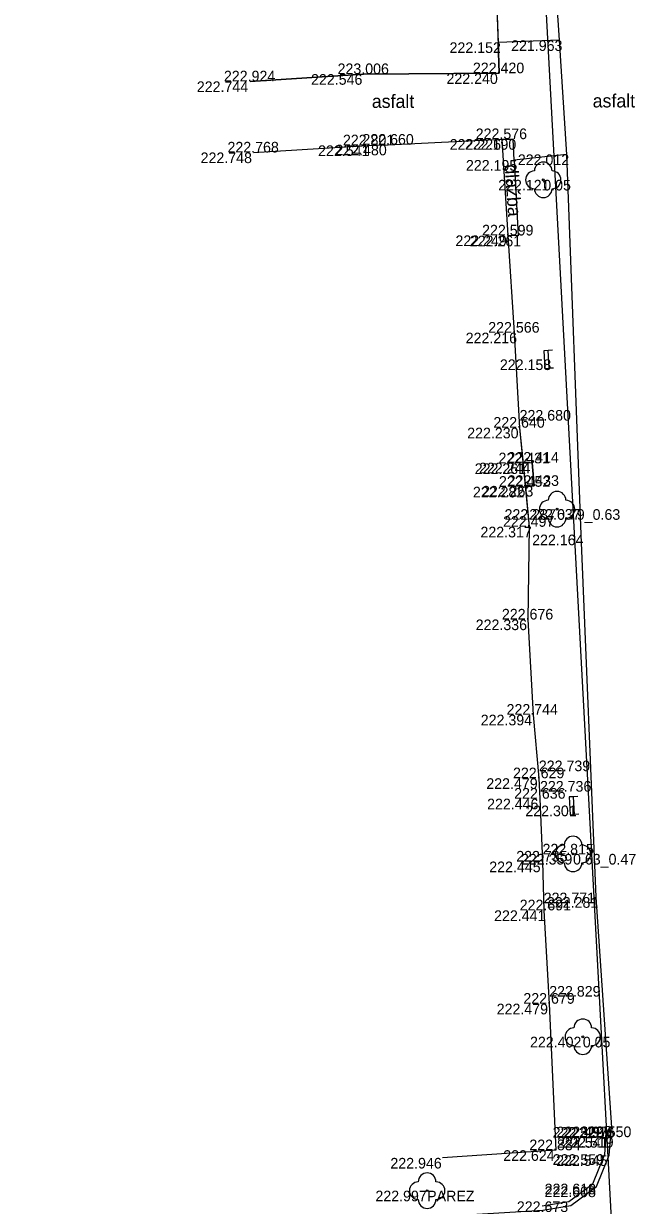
# Model space of a CAD drawing. Extents: x -599516 to -599132, y -1163668 to -1163119.
# Drawn here: x -599301.88 to -599284.57, y -1163560.2 to -1163526.85 of the extents above; entities that cross this region are included whole.
import ezdxf

# ---------------------------------------------------------------- set-up
doc = ezdxf.new("R2010")
doc.units = 0
for name, color, linetype in [('_ZEMERENI OBLAST', 7, 'Continuous'), ('Bod-oznac1', 7, 'Continuous'), ('Bod-oznac2', 7, 'Continuous'), ('Bod-oznac3', 7, 'Continuous'), ('Bod-vyska1', 7, 'Continuous'), ('Bod-vyska2', 7, 'Continuous'), ('Bod-vyska3', 7, 'Continuous'), ('Z_cela-hrobu-dolni-linie', 7, 'Continuous'), ('Z_cela-hrobu-horni-linie', 7, 'Continuous'), ('Z_chodnik', 7, 'Continuous'), ('Z_komunikace', 7, 'Continuous'), ('Z_nove-stromy-prumer-kmene', 7, 'Continuous'), ('Z_obvod-kmene-spodek-ve-vysce1_2m', 7, 'Continuous'), ('Z_parez-stromu', 7, 'Continuous'), ('Z_popis-budov-povrchu', 7, 'Continuous'), ('Z_stromy-kere', 7, 'Continuous'), ('Z_stromy-nove-vysazene', 7, 'Continuous'), ('Z_vol-lin-obrubnik', 7, 'Continuous'), ('Z_znacky-ostatni-lavicka', 7, 'Continuous'), ('Z_zpevnene-plochy', 7, 'Continuous')]:
    doc.layers.add(name, color=color, linetype=linetype)

msp = doc.modelspace()

# ---------------------------------------------------------------- linework, layer by layer
at = {"layer": '_ZEMERENI OBLAST'}
msp.add_lwpolyline([(-599497.946, -1163390.674), (-599491.96, -1163502.01), (-599489.976, -1163538.978), (-599287.834, -1163513.31), (-599283.12, -1163600.69), (-599345.275, -1163603.707), (-599342.31, -1163660.29), (-599277.306, -1163657.294), (-599220.632, -1163654.171)], dxfattribs=at)
at = {"layer": 'Bod-oznac1'}
for p, q in [((-599288.47, -1163527.374), (-599288.47, -1163527.374)), ((-599286.754, -1163527.316), (-599286.754, -1163527.316)), ((-599292.277, -1163528.271), (-599292.277, -1163528.271)), ((-599288.443, -1163528.247), (-599288.443, -1163528.247)), ((-599295.479, -1163528.477), (-599295.479, -1163528.477)), ((-599292.171, -1163530.282), (-599292.171, -1163530.282)), ((-599291.58, -1163530.263), (-599291.58, -1163530.263)), ((-599288.373, -1163530.106), (-599288.373, -1163530.106)), ((-599288.05, -1163530.105), (-599288.05, -1163530.105)), ((-599295.383, -1163530.483), (-599295.383, -1163530.483)), ((-599286.543, -1163530.537), (-599286.543, -1163530.537)), ((-599288.019, -1163530.696), (-599288.019, -1163530.696)), ((-599287.2, -1163531.255), (-599287.2, -1163531.255)), ((-599288.199, -1163532.825), (-599288.199, -1163532.825)), ((-599287.91, -1163532.832), (-599287.91, -1163532.832)), ((-599288.026, -1163535.569), (-599288.026, -1163535.569)), ((-599287.048, -1163536.324), (-599287.048, -1163536.324)), ((-599287.869, -1163538.251), (-599287.869, -1163538.251)), ((-599287.771, -1163539.258), (-599287.771, -1163539.258)), ((-599287.511, -1163539.239), (-599287.511, -1163539.239)), ((-599287.706, -1163539.919), (-599287.706, -1163539.919)), ((-599287.461, -1163539.894), (-599287.461, -1163539.894)), ((-599286.811, -1163540.551), (-599286.811, -1163540.551)), ((-599287.596, -1163541.048), (-599287.596, -1163541.048)), ((-599286.137, -1163541.269), (-599286.137, -1163541.269)), ((-599287.639, -1163543.665), (-599287.639, -1163543.665)), ((-599287.484, -1163546.353), (-599287.484, -1163546.353)), ((-599287.326, -1163548.146), (-599287.326, -1163548.146)), ((-599287.293, -1163548.723), (-599287.293, -1163548.723)), ((-599286.331, -1163548.917), (-599286.331, -1163548.917)), ((-599286.36, -1163550.281), (-599286.36, -1163550.281)), ((-599287.222, -1163550.497), (-599287.222, -1163550.497)), ((-599285.718, -1163551.502), (-599285.718, -1163551.502)), ((-599287.189, -1163551.875), (-599287.189, -1163551.875)), ((-599287.033, -1163554.51), (-599287.033, -1163554.51)), ((-599286.084, -1163555.443), (-599286.084, -1163555.443)), ((-599285.466, -1163557.993), (-599285.466, -1163557.993)), ((-599285.422, -1163558.275), (-599285.422, -1163558.275)), ((-599285.344, -1163557.979), (-599285.344, -1163557.979)), ((-599285.299, -1163558.271), (-599285.299, -1163558.271)), ((-599285.275, -1163558), (-599285.275, -1163558)), ((-599290.048, -1163558.861), (-599290.048, -1163558.861)), ((-599286.848, -1163558.645), (-599286.848, -1163558.645)), ((-599285.465, -1163558.758), (-599285.465, -1163558.758)), ((-599285.344, -1163558.787), (-599285.344, -1163558.787)), ((-599285.796, -1163559.59), (-599285.796, -1163559.59)), ((-599290.48, -1163559.787), (-599290.48, -1163559.787)), ((-599285.695, -1163559.669), (-599285.695, -1163559.669)), ((-599286.475, -1163560.089), (-599286.475, -1163560.089))]:
    msp.add_line(p, q, dxfattribs=at)
at = {"layer": 'Bod-oznac2'}
for p, q in [((-599292.277, -1163528.271), (-599292.277, -1163528.271)), ((-599288.443, -1163528.247), (-599288.443, -1163528.247)), ((-599295.479, -1163528.477), (-599295.479, -1163528.477)), ((-599292.171, -1163530.282), (-599292.171, -1163530.282)), ((-599291.58, -1163530.263), (-599291.58, -1163530.263)), ((-599288.373, -1163530.106), (-599288.373, -1163530.106)), ((-599295.383, -1163530.483), (-599295.383, -1163530.483)), ((-599288.199, -1163532.825), (-599288.199, -1163532.825)), ((-599288.026, -1163535.569), (-599288.026, -1163535.569)), ((-599287.869, -1163538.251), (-599287.869, -1163538.251)), ((-599287.771, -1163539.258), (-599287.771, -1163539.258)), ((-599287.511, -1163539.239), (-599287.511, -1163539.239)), ((-599287.706, -1163539.919), (-599287.706, -1163539.919)), ((-599287.461, -1163539.894), (-599287.461, -1163539.894)), ((-599287.596, -1163541.048), (-599287.596, -1163541.048)), ((-599287.639, -1163543.665), (-599287.639, -1163543.665)), ((-599287.484, -1163546.353), (-599287.484, -1163546.353)), ((-599287.326, -1163548.146), (-599287.326, -1163548.146)), ((-599287.293, -1163548.723), (-599287.293, -1163548.723)), ((-599287.222, -1163550.497), (-599287.222, -1163550.497)), ((-599287.189, -1163551.875), (-599287.189, -1163551.875)), ((-599287.033, -1163554.51), (-599287.033, -1163554.51)), ((-599285.422, -1163558.275), (-599285.422, -1163558.275)), ((-599286.848, -1163558.645), (-599286.848, -1163558.645))]:
    msp.add_line(p, q, dxfattribs=at)
at = {"layer": 'Bod-oznac3'}
for p, q in [((-599287.869, -1163538.251), (-599287.869, -1163538.251)), ((-599287.596, -1163541.048), (-599287.596, -1163541.048)), ((-599287.326, -1163548.146), (-599287.326, -1163548.146)), ((-599287.293, -1163548.723), (-599287.293, -1163548.723)), ((-599287.222, -1163550.497), (-599287.222, -1163550.497)), ((-599287.189, -1163551.875), (-599287.189, -1163551.875)), ((-599287.033, -1163554.51), (-599287.033, -1163554.51))]:
    msp.add_line(p, q, dxfattribs=at)
at = {"layer": 'Z_cela-hrobu-dolni-linie'}
for points in [[(-599289.572, -1163505.857), (-599289.403, -1163508.572), (-599289.336, -1163509.711), (-599289.308, -1163510.254), (-599289.258, -1163511.445), (-599289.147, -1163514.133), (-599289.014, -1163515.172), (-599288.989, -1163516.052), (-599288.949, -1163517.063), (-599288.92, -1163517.922), (-599288.855, -1163518.98), (-599288.811, -1163519.843), (-599288.746, -1163520.956), (-599288.724, -1163521.528), (-599288.689, -1163522.629), (-599288.546, -1163525.359), (-599288.47, -1163527.374), (-599288.443, -1163528.247)], [(-599288.373, -1163530.106), (-599288.199, -1163532.825), (-599288.026, -1163535.569), (-599287.869, -1163538.251), (-599287.771, -1163539.258), (-599287.706, -1163539.919), (-599287.596, -1163541.048), (-599287.639, -1163543.665), (-599287.484, -1163546.353), (-599287.326, -1163548.146), (-599287.293, -1163548.723), (-599287.222, -1163550.497), (-599287.189, -1163551.875), (-599287.033, -1163554.51), (-599286.848, -1163558.645), (-599290.048, -1163558.861)]]:
    msp.add_lwpolyline(points, dxfattribs=at)
at = {"layer": 'Z_cela-hrobu-horni-linie'}
for points in [[(-599288.546, -1163525.359), (-599288.443, -1163528.247), (-599292.277, -1163528.271)], [(-599292.277, -1163528.271), (-599295.479, -1163528.477)], [(-599295.383, -1163530.483), (-599292.171, -1163530.282), (-599291.58, -1163530.263), (-599288.373, -1163530.106), (-599288.199, -1163532.825), (-599288.026, -1163535.569), (-599287.869, -1163538.251), (-599287.869, -1163538.251), (-599287.596, -1163541.048), (-599287.596, -1163541.048), (-599287.639, -1163543.665), (-599287.484, -1163546.353), (-599287.326, -1163548.146), (-599287.326, -1163548.146), (-599287.293, -1163548.723), (-599287.293, -1163548.723), (-599287.222, -1163550.497), (-599287.222, -1163550.497), (-599287.189, -1163551.875), (-599287.189, -1163551.875), (-599287.033, -1163554.51), (-599287.033, -1163554.51), (-599286.848, -1163558.645), (-599290.048, -1163558.861)]]:
    msp.add_lwpolyline(points, dxfattribs=at)
at = {"layer": 'Z_chodnik'}
for points in [[(-599295.479, -1163528.477), (-599292.277, -1163528.271), (-599288.443, -1163528.247), (-599288.47, -1163527.374)], [(-599286.754, -1163527.316), (-599288.47, -1163527.374)], [(-599295.383, -1163530.483), (-599292.171, -1163530.282), (-599291.58, -1163530.263), (-599288.373, -1163530.106), (-599288.05, -1163530.105)], [(-599286.543, -1163530.537), (-599288.019, -1163530.696), (-599288.05, -1163530.105)]]:
    msp.add_lwpolyline(points, dxfattribs=at)
at = {"layer": 'Z_komunikace'}
for points in [[(-599289.978, -1163500.153), (-599289.346, -1163500.218), (-599288.913, -1163500.474), (-599288.386, -1163501.431), (-599288.16, -1163505.442), (-599288.036, -1163507.473), (-599287.478, -1163516.528), (-599286.754, -1163527.316), (-599286.543, -1163530.537), (-599286.137, -1163541.269), (-599285.718, -1163551.502), (-599285.275, -1163558)], [(-599291.24, -1163560.577), (-599287.217, -1163560.34), (-599286.426, -1163560.206), (-599285.695, -1163559.669), (-599285.344, -1163558.787), (-599285.275, -1163558)]]:
    msp.add_lwpolyline(points, dxfattribs=at)
at = {"layer": 'Z_parez-stromu'}
msp.add_circle((-599290.48, -1163559.787), 0.025, dxfattribs=at)
for centre, start, end in [((-599290.48, -1163559.537), 0, 180), ((-599290.73, -1163559.787), 90, 270), ((-599290.23, -1163559.787), 270, 90), ((-599290.48, -1163560.037), 180, 0)]:
    msp.add_arc(centre, 0.25, start, end, dxfattribs=at)
at = {"layer": 'Z_stromy-kere'}
for centre in [(-599286.811, -1163540.551), (-599286.36, -1163550.281)]:
    msp.add_circle(centre, 0.025, dxfattribs=at)
for centre, start, end in [((-599286.811, -1163540.301), 0, 180), ((-599287.061, -1163540.551), 90, 270), ((-599286.561, -1163540.551), 270, 90), ((-599286.811, -1163540.801), 180, 0), ((-599286.36, -1163550.031), 0, 180), ((-599286.61, -1163550.281), 90, 270), ((-599286.11, -1163550.281), 270, 90), ((-599286.36, -1163550.531), 180, 0)]:
    msp.add_arc(centre, 0.25, start, end, dxfattribs=at)
at = {"layer": 'Z_stromy-nove-vysazene'}
for centre in [(-599287.2, -1163531.255), (-599286.084, -1163555.443)]:
    msp.add_circle(centre, 0.025, dxfattribs=at)
for centre, start, end in [((-599287.2, -1163531.005), 0, 180), ((-599287.45, -1163531.255), 90, 270), ((-599286.95, -1163531.255), 270, 90), ((-599287.2, -1163531.505), 180, 0), ((-599286.084, -1163555.193), 0, 180), ((-599286.334, -1163555.443), 90, 270), ((-599285.834, -1163555.443), 270, 90), ((-599286.084, -1163555.693), 180, 0)]:
    msp.add_arc(centre, 0.25, start, end, dxfattribs=at)
at = {"layer": 'Z_vol-lin-obrubnik'}
for points in [[(-599287.233, -1163560.217), (-599286.475, -1163560.089), (-599285.796, -1163559.59), (-599285.465, -1163558.758), (-599285.422, -1163558.275)], [(-599285.344, -1163557.979), (-599285.466, -1163557.993), (-599285.422, -1163558.275)], [(-599285.344, -1163557.979), (-599285.299, -1163558.271)]]:
    msp.add_lwpolyline(points, dxfattribs=at)
at = {"layer": 'Z_znacky-ostatni-lavicka'}
for p, q in [((-599286.937, -1163536.067), (-599287.062, -1163536.074)), ((-599286.909, -1163536.567), (-599287.034, -1163536.574)), ((-599286.22, -1163548.66), (-599286.345, -1163548.667)), ((-599286.192, -1163549.16), (-599286.317, -1163549.167))]:
    msp.add_line(p, q, dxfattribs=at)
for points in [[(-599287.159, -1163536.581), (-599287.034, -1163536.574), (-599287.062, -1163536.074), (-599287.187, -1163536.081)], [(-599286.442, -1163549.174), (-599286.317, -1163549.167), (-599286.345, -1163548.667), (-599286.47, -1163548.674)]]:
    msp.add_lwpolyline(points, close=True, dxfattribs=at)
at = {"layer": 'Z_zpevnene-plochy'}
for p, q in [((-599287.511, -1163539.239), (-599287.771, -1163539.258)), ((-599287.461, -1163539.894), (-599287.706, -1163539.919))]:
    msp.add_line(p, q, dxfattribs=at)
for points in [[(-599288.019, -1163530.696), (-599287.91, -1163532.832), (-599288.199, -1163532.825)], [(-599287.706, -1163539.919), (-599287.461, -1163539.894), (-599287.511, -1163539.239), (-599287.771, -1163539.258)], [(-599287.511, -1163539.239), (-599287.461, -1163539.894)]]:
    msp.add_lwpolyline(points, dxfattribs=at)

# ---------------------------------------------------------------- texts
at = {"layer": 'Bod-vyska1'}
for s, p in [('222.152', (-599289.848, -1163527.674)), ('221.963', (-599288.109, -1163527.616)), ('222.546', (-599293.759, -1163528.571)), ('222.240', (-599289.934, -1163528.547)), ('222.744', (-599296.985, -1163528.777)), ('222.541', (-599293.56, -1163530.582)), ('222.480', (-599293.071, -1163530.563)), ('222.226', (-599289.843, -1163530.406)), ('222.190', (-599289.414, -1163530.405)), ('222.748', (-599296.878, -1163530.783)), ('222.012', (-599287.919, -1163530.837)), ('222.195', (-599289.385, -1163530.996)), ('222.121', (-599288.474, -1163531.555)), ('222.249', (-599289.681, -1163533.125)), ('222.261', (-599289.276, -1163533.132)), ('222.216', (-599289.392, -1163535.869)), ('222.158', (-599288.426, -1163536.624)), ('222.230', (-599289.349, -1163538.551)), ('222.261', (-599289.137, -1163539.558)), ('222.244', (-599289.015, -1163539.539)), ('222.282', (-599289.188, -1163540.219)), ('222.263', (-599288.931, -1163540.194)), ('222.237', (-599288.294, -1163540.851)), ('222.317', (-599288.975, -1163541.348)), ('222.164', (-599287.515, -1163541.569)), ('222.336', (-599289.109, -1163543.965)), ('222.394', (-599288.966, -1163546.653)), ('222.479', (-599288.809, -1163548.446)), ('222.446', (-599288.786, -1163549.023)), ('222.301', (-599287.707, -1163549.217)), ('222.359', (-599287.83, -1163550.581)), ('222.445', (-599288.726, -1163550.797)), ('222.281', (-599287.096, -1163551.802)), ('222.441', (-599288.589, -1163552.175)), ('222.479', (-599288.516, -1163554.81)), ('222.402', (-599287.575, -1163555.743)), ('222.529', (-599286.936, -1163558.293)), ('222.497', (-599286.827, -1163558.279)), ('222.541', (-599286.811, -1163558.575)), ('222.519', (-599286.665, -1163558.571)), ('222.516', (-599286.641, -1163558.3)), ('222.946', (-599291.518, -1163559.161)), ('222.624', (-599288.33, -1163558.945)), ('222.559', (-599286.935, -1163559.058)), ('222.545', (-599286.837, -1163559.087)), ('222.618', (-599287.162, -1163559.89)), ('222.997', (-599291.941, -1163560.087)), ('222.608', (-599287.163, -1163559.969)), ('222.673', (-599287.947, -1163560.389))]:
    msp.add_text(s, height=0.3, dxfattribs=at).set_placement(p)
at = {"layer": 'Bod-vyska2'}
for s, p in [('222.420', (-599289.188, -1163528.247)), ('222.924', (-599296.22, -1163528.477)), ('223.006', (-599293.01, -1163528.271)), ('222.576', (-599289.109, -1163530.106)), ('222.768', (-599296.119, -1163530.483)), ('222.801', (-599292.859, -1163530.282)), ('222.660', (-599292.308, -1163530.263)), ('222.599', (-599288.928, -1163532.825)), ('222.566', (-599288.755, -1163535.569)), ('222.640', (-599288.609, -1163538.251)), ('222.431', (-599288.465, -1163539.258)), ('222.414', (-599288.211, -1163539.239)), ('222.452', (-599288.452, -1163539.919)), ('222.433', (-599288.207, -1163539.894)), ('222.497', (-599288.338, -1163541.048)), ('222.676', (-599288.369, -1163543.665)), ('222.744', (-599288.237, -1163546.353)), ('222.629', (-599288.055, -1163548.146)), ('222.636', (-599288.022, -1163548.723)), ('222.735', (-599287.964, -1163550.497)), ('222.691', (-599287.866, -1163551.875)), ('222.679', (-599287.763, -1163554.51)), ('222.550', (-599286.162, -1163558.275)), ('222.834', (-599287.594, -1163558.645))]:
    msp.add_text(s, height=0.3, dxfattribs=at).set_placement(p)
at = {"layer": 'Bod-vyska3'}
for s, p in [('222.680', (-599287.869, -1163538.051)), ('222.637', (-599287.596, -1163540.848)), ('222.739', (-599287.326, -1163547.946)), ('222.736', (-599287.293, -1163548.523)), ('222.815', (-599287.222, -1163550.297)), ('222.771', (-599287.189, -1163551.675)), ('222.829', (-599287.033, -1163554.31))]:
    msp.add_text(s, height=0.3, dxfattribs=at).set_placement(p)
at = {"layer": 'Z_nove-stromy-prumer-kmene'}
for p in [(-599287.2, -1163531.555), (-599286.084, -1163555.743)]:
    msp.add_text('0.05', height=0.3, dxfattribs=at).set_placement(p)
at = {"layer": 'Z_obvod-kmene-spodek-ve-vysce1_2m'}
for s, p in [('0.79_0.63', (-599286.811, -1163540.851)), ('0.63_0.47', (-599286.36, -1163550.581)), ('PAREZ', (-599290.48, -1163560.087))]:
    msp.add_text(s, height=0.3, dxfattribs=at).set_placement(p)
at = {"layer": 'Z_popis-budov-povrchu'}
for p in [(-599292.042, -1163529.225), (-599285.805, -1163529.212)]:
    msp.add_text('asfalt', height=0.375, dxfattribs=at).set_placement(p)
msp.add_text('dlažba', height=0.375, rotation=273.9346, dxfattribs=at).set_placement((-599288.292, -1163530.83))

doc.saveas('drawing.dxf')
